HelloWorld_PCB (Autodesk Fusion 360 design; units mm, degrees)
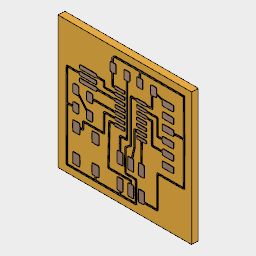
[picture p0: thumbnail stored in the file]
sketch "Sketch1"
  line L1 (27.7162, -34.7143) -> (27.9875, -34.4404)
  line L2 (27.4454, -34.9877) -> (27.7162, -34.7143)
  line L3 (27.4542, -35.5003) -> (27.4454, -34.9877)
  line L4 (27.4629, -36.0068) -> (27.4542, -35.5003)
  line L5 (27.2733, -36.0068) -> (27.4629, -36.0068)
  curve K1 (27.1043, -36.0259) -> (27.2733, -36.0068)
  curve K2 (27.034, -36.1184) -> (27.1043, -36.0259)
  curve K3 (27.0134, -36.2527) -> (27.034, -36.1184)
  curve K4 (26.9999, -36.5003) -> (27.0134, -36.2527)
  curve K5 (26.9917, -37.1814) -> (26.9999, -36.5003)
  curve K6 (27.0072, -37.8464) -> (26.9917, -37.1814)
  curve K7 (27.0237, -38.0754) -> (27.0072, -37.8464)
  curve K8 (27.0341, -38.1467) -> (27.0237, -38.0754)
  curve K9 (27.0465, -38.1834) -> (27.0341, -38.1467)
  curve K10 (27.1354, -38.2381) -> (27.0465, -38.1834)
  curve K11 (27.2718, -38.2676) -> (27.1354, -38.2381)
  line L6 (27.4371, -38.28) -> (27.2718, -38.2676)
  line L7 (27.4454, -39.6665) -> (27.4371, -38.28)
  curve K12 (27.4966, -41.053) -> (27.4454, -39.6665)
  curve K13 (27.619, -41.2085) -> (27.4966, -41.053)
  curve K14 (27.8614, -41.2225) -> (27.619, -41.2085)
  curve K15 (28.0815, -41.2385) -> (27.8614, -41.2225)
  curve K16 (28.158, -41.315) -> (28.0815, -41.2385)
  curve K17 (28.2025, -41.3723) -> (28.158, -41.315)
  curve K18 (28.3471, -41.4023) -> (28.2025, -41.3723)
  curve K19 (29.3957, -41.424) -> (28.3471, -41.4023)
  curve K20 (30.3946, -41.4219) -> (29.3957, -41.424)
  curve K21 (30.5811, -41.4027) -> (30.3946, -41.4219)
  curve K22 (30.6581, -41.3666) -> (30.5811, -41.4027)
  curve K23 (30.7134, -41.2059) -> (30.6581, -41.3666)
  curve K24 (30.7315, -40.9428) -> (30.7134, -41.2059)
  curve K25 (30.6581, -40.5191) -> (30.7134, -40.6798)
  curve K26 (30.5811, -40.4829) -> (30.6581, -40.5191)
  curve K27 (30.3946, -40.4638) -> (30.5811, -40.4829)
  curve K28 (29.3957, -40.4617) -> (30.3946, -40.4638)
  curve K29 (28.3471, -40.4834) -> (29.3957, -40.4617)
  curve K30 (28.2025, -40.5133) -> (28.3471, -40.4834)
  curve K31 (28.158, -40.5707) -> (28.2025, -40.5133)
  curve K32 (28.1074, -40.6363) -> (28.158, -40.5707)
  curve K33 (28.0454, -40.6632) -> (28.1074, -40.6363)
  curve K34 (28.0242, -40.6585) -> (28.0454, -40.6632)
  curve K35 (28.0081, -40.6358) -> (28.0242, -40.6585)
  curve K36 (27.9859, -40.4859) -> (28.0081, -40.6358)
  curve K37 (27.9751, -39.4627) -> (27.9859, -40.4859)
  line L8 (27.9751, -38.2623) -> (27.9751, -39.4627)
  line L9 (28.2991, -38.2499) -> (27.9751, -38.2623)
  line L10 (28.6308, -38.2375) -> (28.2991, -38.2499)
  line L11 (28.6427, -37.2174) -> (28.6308, -38.2375)
  curve K38 (28.6443, -36.4717) -> (28.6427, -37.2174)
  curve K39 (28.6396, -36.2231) -> (28.6443, -36.4717)
  curve K40 (28.636, -36.1456) -> (28.6396, -36.2231)
  curve K41 (28.6314, -36.1053) -> (28.636, -36.1456)
  curve K42 (28.6097, -36.0516) -> (28.6314, -36.1053)
  curve K43 (28.5606, -36.0216) -> (28.6097, -36.0516)
  curve K44 (28.2872, -36.0066) -> (28.5606, -36.0216)
  line L12 (27.9751, -36.0066) -> (28.2872, -36.0066)
  line L13 (27.9751, -35.6144) -> (27.9751, -36.0066)
  line L14 (27.9751, -35.2191) -> (27.9751, -35.6144)
  line L15 (28.1632, -35.046) -> (27.9751, -35.2191)
  line L16 (28.3513, -34.8723) -> (28.1632, -35.046)
  line L17 (31.1341, -34.8723) -> (28.3513, -34.8723)
  line L18 (33.9143, -34.8723) -> (31.1341, -34.8723)
  line L19 (33.9013, -35.4392) -> (33.9143, -34.8723)
  line L20 (33.8884, -36.0066) -> (33.9013, -35.4392)
  line L21 (33.6636, -36.0066) -> (33.8884, -36.0066)
  curve K45 (33.4704, -36.0232) -> (33.6636, -36.0066)
  curve K46 (33.3872, -36.0909) -> (33.4704, -36.0232)
  curve K47 (33.3763, -36.1322) -> (33.3872, -36.0909)
  curve K48 (33.367, -36.2087) -> (33.3763, -36.1322)
  curve K49 (33.3536, -36.4485) -> (33.367, -36.2087)
  curve K50 (33.3422, -37.1326) -> (33.3536, -36.4485)
  curve K51 (33.3536, -37.8168) -> (33.3422, -37.1326)
  curve K52 (33.367, -38.0566) -> (33.3536, -37.8168)
  curve K53 (33.3763, -38.1331) -> (33.367, -38.0566)
  curve K54 (33.3872, -38.175) -> (33.3763, -38.1331)
  curve K55 (33.4321, -38.2215) -> (33.3872, -38.175)
  curve K56 (33.5417, -38.2463) -> (33.4321, -38.2215)
  curve K57 (34.1907, -38.2587) -> (33.5417, -38.2463)
  curve K58 (34.8176, -38.2468) -> (34.1907, -38.2587)
  curve K59 (34.9338, -38.2266) -> (34.8176, -38.2468)
  curve K60 (34.9762, -38.1894) -> (34.9338, -38.2266)
  curve K61 (34.9814, -38.1543) -> (34.9762, -38.1894)
  curve K62 (34.9865, -38.0825) -> (34.9814, -38.1543)
  curve K63 (34.9948, -37.8458) -> (34.9865, -38.0825)
  curve K64 (35.002, -37.1166) -> (34.9948, -37.8458)
  curve K65 (34.9906, -36.3311) -> (35.002, -37.1166)
  curve K66 (34.9746, -36.1394) -> (34.9906, -36.3311)
  curve K67 (34.9638, -36.0867) -> (34.9746, -36.1394)
  curve K68 (34.9503, -36.0588) -> (34.9638, -36.0867)
  curve K69 (34.911, -36.0381) -> (34.9503, -36.0588)
  curve K70 (34.8459, -36.0216) -> (34.911, -36.0381)
  curve K71 (34.6718, -36.0066) -> (34.8459, -36.0216)
  line L22 (34.4516, -36.0066) -> (34.6718, -36.0066)
  line L23 (34.4516, -35.5581) -> (34.4516, -36.0066)
  curve K72 (34.4677, -35.1535) -> (34.4516, -35.5581)
  curve K73 (34.5643, -34.9896) -> (34.4677, -35.1535)
  line L24 (34.6769, -34.8723) -> (34.5643, -34.9896)
  line L25 (39.5567, -34.8723) -> (34.6769, -34.8723)
  line L26 (44.434, -34.8723) -> (39.5567, -34.8723)
  line L27 (44.434, -39.038) -> (44.434, -34.8723)
  line L28 (44.434, -43.2036) -> (44.434, -39.038)
  line L29 (43.3798, -43.2036) -> (44.434, -43.2036)
  line L30 (42.3256, -43.2036) -> (43.3798, -43.2036)
  line L31 (42.3256, -42.9835) -> (42.3256, -43.2036)
  curve K74 (42.3106, -42.8093) -> (42.3256, -42.9835)
  curve K75 (42.2946, -42.7442) -> (42.3106, -42.8093)
  curve K76 (42.2739, -42.7049) -> (42.2946, -42.7442)
  curve K77 (42.2579, -42.6977) -> (42.2739, -42.7049)
  curve K78 (42.229, -42.691) -> (42.2579, -42.6977)
  curve K79 (42.1339, -42.6801) -> (42.229, -42.691)
  curve K80 (41.8166, -42.6631) -> (42.1339, -42.6801)
  curve K81 (40.8823, -42.6496) -> (41.8166, -42.6631)
  curve K82 (39.948, -42.6631) -> (40.8823, -42.6496)
  curve K83 (39.6307, -42.6801) -> (39.948, -42.6631)
  curve K84 (39.5356, -42.691) -> (39.6307, -42.6801)
  curve K85 (39.5067, -42.6977) -> (39.5356, -42.691)
  curve K86 (39.4906, -42.7049) -> (39.5067, -42.6977)
  curve K87 (39.4772, -42.7354) -> (39.4906, -42.7049)
  curve K88 (39.4663, -42.7917) -> (39.4772, -42.7354)
  curve K89 (39.4493, -42.97) -> (39.4663, -42.7917)
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extrude "Extrude1" new body sketch "Sketch1" blind 0.1
sketch "Sketch2"
sketch "Sketch3"
  line L1 (46.4347, -32.8573) -> (14.6752, -32.8573)
  line L2 (46.4347, -64.2884) -> (46.4347, -32.8573)
  line L3 (14.6752, -64.2884) -> (46.4347, -64.2884)
  line L4 (14.6752, -32.8573) -> (14.6752, -64.2884)
extrude "Extrude2" new body sketch "Sketch3" blind -1.6
sketch "Sketch4" plane through (0, 0, 0.1) normal (0, 0, 1) x axis (1, 0, 0)
  curve K1 (19.8964, -40.4673) -> (19.9119, -40.4621)
  curve K2 (19.8903, -41.2941) -> (19.8722, -41.2766)
  curve K3 (20.2138, -41.3298) -> (19.943, -41.3096)
  curve K4 (21.8493, -41.3406) -> (20.2138, -41.3298)
  curve K5 (23.6415, -41.3179) -> (21.8493, -41.3406)
  curve K6 (23.8688, -41.2657) -> (23.6415, -41.3179)
  curve K7 (23.8978, -41.2244) -> (23.8688, -41.2657)
  curve K8 (23.9024, -41.167) -> (23.8978, -41.2244)
  curve K9 (23.9066, -41.1417) -> (23.9024, -41.167)
  curve K10 (23.9252, -41.1221) -> (23.9066, -41.1417)
  curve K11 (24.0285, -41.0983) -> (23.9252, -41.1221)
  curve K12 (24.7106, -41.0869) -> (24.0285, -41.0983)
  line L1 (25.5194, -41.0869) -> (24.7106, -41.0869)
  line L2 (25.5194, -41.6595) -> (25.5194, -41.0869)
  curve K13 (25.5323, -42.1287) -> (25.5194, -41.6595)
  curve K14 (25.5845, -42.2915) -> (25.5323, -42.1287)
  curve K15 (25.6625, -42.3251) -> (25.5845, -42.2915)
  curve K16 (25.8661, -42.3453) -> (25.6625, -42.3251)
  curve K17 (26.9575, -42.3566) -> (25.8661, -42.3453)
  curve K18 (28.0779, -42.368) -> (26.9575, -42.3566)
  curve K19 (28.2386, -42.3918) -> (28.0779, -42.368)
  curve K20 (28.2649, -42.4119) -> (28.2386, -42.3918)
  curve K21 (28.2711, -42.4388) -> (28.2649, -42.4119)
  curve K22 (28.3001, -42.5427) -> (28.2985, -42.5422)
  curve K23 (28.3053, -42.5437) -> (28.3001, -42.5427)
  curve K24 (28.3249, -42.5464) -> (28.3053, -42.5437)
  curve K25 (28.3962, -42.5515) -> (28.3249, -42.5464)
  line L3 (30.5697, -42.5474) -> (29.4494, -42.5588)
  line L4 (30.5697, -41.8787) -> (30.5697, -42.5474)
  line L5 (28.2918, -41.8787) -> (30.5697, -41.8787)
  line L6 (28.2789, -41.9702) -> (28.2918, -41.8787)
  line L7 (28.2644, -42.0689) -> (28.2789, -41.9702)
  line L8 (25.8072, -42.0689) -> (28.2644, -42.0689)
  line L9 (25.8072, -41.4808) -> (25.8072, -42.0689)
  curve K26 (25.7948, -41.0271) -> (25.8072, -41.4808)
  curve K27 (25.7793, -40.9041) -> (25.7948, -41.0271)
  curve K28 (24.8083, -40.7992) -> (25.5127, -40.8106)
  line L10 (23.9024, -40.7992) -> (24.8083, -40.7992)
  line L11 (23.9024, -40.655) -> (23.9024, -40.7992)
  curve K29 (23.8373, -40.4623) -> (23.8528, -40.4674)
  curve K30 (23.7996, -40.4561) -> (23.8373, -40.4623)
  line L12 (21.8746, -40.4136) -> (21.8747, -40.4137)
  line L13 (23.9323, -41.2941) -> (19.7785, -41.2941)
  line L14 (23.9323, -41.7957) -> (23.9323, -41.2941)
  line L15 (19.7785, -41.7957) -> (23.9323, -41.7957)
  line L16 (19.7785, -41.2941) -> (19.7785, -41.7957)
  line L17 (23.843, -42.6463) -> (19.8614, -42.6463)
  line L18 (23.843, -43.1443) -> (23.843, -42.6463)
  line L19 (19.8614, -43.1443) -> (23.843, -43.1443)
  line L20 (19.8614, -42.6463) -> (19.8614, -43.1443)
  closed curve K31 centre (21.8178, -40.4603)
  closed curve K32 centre (28.5702, -40.6016)
  closed curve K33 centre (20.2242, -40.4595)
  closed curve K34 centre (20.1295, -40.464)
  closed curve K35 centre (19.8883, -40.5327)
  closed curve K36 centre (19.8888, -40.6445)
  closed curve K37 centre (19.8937, -40.9387)
  closed curve K38 centre (19.8884, -40.8615)
  closed curve K39 centre (19.9055, -40.8172)
  closed curve K40 centre (20.307, -41.2306)
  closed curve K41 centre (28.3011, -42.4664)
  closed curve K42 centre (28.2936, -42.4865)
  closed curve K43 centre (29.788, -42.5224)
  closed curve K44 centre (29.4419, -42.5276)
  closed curve K45 centre (25.7583, -40.9593)
  closed curve K46 centre (25.6259, -40.8463)
  closed curve K47 centre (24.6126, -40.9088)
  closed curve K48 centre (23.8506, -40.5987)
  closed curve K49 centre (23.8586, -40.5824)
  closed curve K50 centre (23.5222, -40.4602)
  closed curve K51 centre (15.188, -40.6015)
  closed curve K52 centre (21.9314, -40.4604)
extrude "Extrude3" cut sketch "Sketch4" profile of K40 K3 K4 K5 K6 L13 L14 L15 L16 L17 L18 L19 L20 against normal blind 0.1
